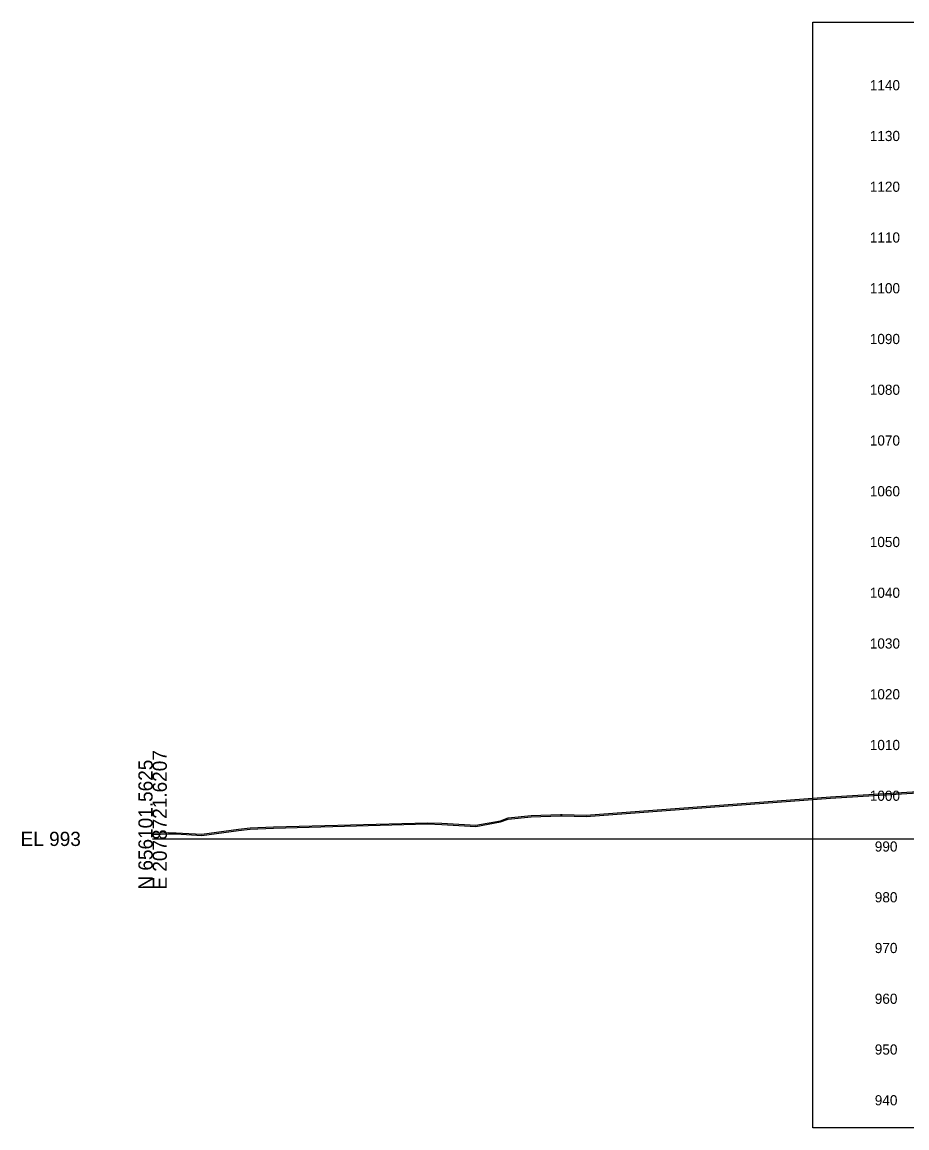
# Model space of a CAD drawing. Extents: x 1131015 to 1136271, y 133453 to 174329.
# Drawn here: x 1131014.8 to 1131189, y 159610.7 to 159828.6 of the extents above; entities that cross this region are included whole.
import ezdxf

# ---------------------------------------------------------------- set-up
doc = ezdxf.new("R2010")
doc.units = 0
for name, color, linetype in [('DESIGN - SHEET - Corner Text', 7, 'Continuous'), ('DESIGN - SHEET - Light Grid', 7, 'Continuous'), ('DESIGN - SHEET - Plot Shape', 7, 'Continuous'), ('SURVEY - GROUND - Bottom of Topsoil Layer', 7, 'Continuous'), ('SURVEY - GROUND - Top of Ground', 7, 'Continuous')]:
    doc.layers.add(name, color=color, linetype=linetype)

msp = doc.modelspace()

# ---------------------------------------------------------------- linework, layer by layer
at = {"layer": 'DESIGN - SHEET - Light Grid'}
msp.add_line((1131040.46, 159667.66), (1131340.46, 159667.66), dxfattribs=at)
at = {"layer": 'DESIGN - SHEET - Plot Shape'}
msp.add_lwpolyline([(1131170.46, 159828.6), (1131510.46, 159828.6), (1131510.46, 159610.72), (1131170.46, 159610.72)], close=True, dxfattribs=at)
at = {"layer": 'SURVEY - GROUND - Bottom of Topsoil Layer'}
for p, q in [((1131125.87, 159672.06), (1131173.95, 159675.67)), ((1131173.95, 159675.67), (1131193.35, 159676.85)), ((1131108.94, 159670.99), (1131110.5, 159671.53)), ((1131110.5, 159671.53), (1131114.98, 159672)), ((1131114.98, 159672), (1131120.81, 159672.21)), ((1131120.81, 159672.21), (1131121.12, 159672.22)), ((1131121.12, 159672.22), (1131125.87, 159672.06)), ((1131050.13, 159668.35), (1131057.4, 159669.31)), ((1131057.4, 159669.31), (1131059.68, 159669.58)), ((1131059.68, 159669.58), (1131064.26, 159669.77)), ((1131064.26, 159669.77), (1131094.6, 159670.6)), ((1131094.6, 159670.6), (1131097.43, 159670.49)), ((1131097.43, 159670.49), (1131104.09, 159670.09)), ((1131104.09, 159670.09), (1131108.94, 159670.99)), ((1131040.46, 159668.55), (1131043.58, 159668.65)), ((1131043.58, 159668.65), (1131045.07, 159668.63)), ((1131045.07, 159668.63), (1131050.13, 159668.35))]:
    msp.add_line(p, q, dxfattribs=at)
at = {"layer": 'SURVEY - GROUND - Top of Ground'}
for p, q in [((1131125.87, 159672.31), (1131173.95, 159675.92)), ((1131173.95, 159675.92), (1131193.35, 159677.1)), ((1131104.09, 159670.34), (1131108.94, 159671.24)), ((1131108.94, 159671.24), (1131110.5, 159671.78)), ((1131110.5, 159671.78), (1131114.98, 159672.25)), ((1131114.98, 159672.25), (1131120.81, 159672.46)), ((1131120.81, 159672.46), (1131121.12, 159672.47)), ((1131121.12, 159672.47), (1131125.87, 159672.31)), ((1131050.13, 159668.6), (1131057.4, 159669.56)), ((1131057.4, 159669.56), (1131059.68, 159669.83)), ((1131059.68, 159669.83), (1131064.26, 159670.02)), ((1131064.26, 159670.02), (1131094.6, 159670.85)), ((1131094.6, 159670.85), (1131097.43, 159670.74)), ((1131097.43, 159670.74), (1131104.09, 159670.34)), ((1131040.46, 159668.8), (1131043.58, 159668.9)), ((1131043.58, 159668.9), (1131045.07, 159668.88)), ((1131045.07, 159668.88), (1131050.13, 159668.6))]:
    msp.add_line(p, q, dxfattribs=at)

# ---------------------------------------------------------------- texts
at = {"layer": 'DESIGN - SHEET - Corner Text'}
for s, p in [('1140', (1131181.7, 159815.16)), ('1130', (1131181.7, 159805.16)), ('1120', (1131181.7, 159795.16)), ('1110', (1131181.7, 159785.16)), ('1100', (1131181.7, 159775.16)), ('1090', (1131181.7, 159765.16)), ('1080', (1131181.7, 159755.16)), ('1070', (1131181.7, 159745.16)), ('1060', (1131181.7, 159735.16)), ('1050', (1131181.7, 159725.16)), ('1040', (1131181.7, 159715.16)), ('1030', (1131181.7, 159705.16)), ('1020', (1131181.7, 159695.16)), ('1010', (1131181.7, 159685.16)), ('1000', (1131181.7, 159675.16)), ('990', (1131182.68, 159665.16)), ('980', (1131182.68, 159655.16)), ('970', (1131182.68, 159645.16)), ('960', (1131182.68, 159635.16)), ('950', (1131182.68, 159625.16)), ('940', (1131182.68, 159615.16))]:
    msp.add_text(s, height=2, dxfattribs=at).set_placement(p)
at = {"layer": 'DESIGN - SHEET - Light Grid'}
for s, p in [('E 2078721.6207', (1131043.26, 159657.66)), ('N 656101.5625', (1131040.46, 159657.66))]:
    msp.add_text(s, height=2.8, rotation=90, dxfattribs=at).set_placement(p)
msp.add_text('EL 993', height=2.8, dxfattribs=at).set_placement((1131014.46, 159666.26))

doc.saveas('drawing.dxf')
